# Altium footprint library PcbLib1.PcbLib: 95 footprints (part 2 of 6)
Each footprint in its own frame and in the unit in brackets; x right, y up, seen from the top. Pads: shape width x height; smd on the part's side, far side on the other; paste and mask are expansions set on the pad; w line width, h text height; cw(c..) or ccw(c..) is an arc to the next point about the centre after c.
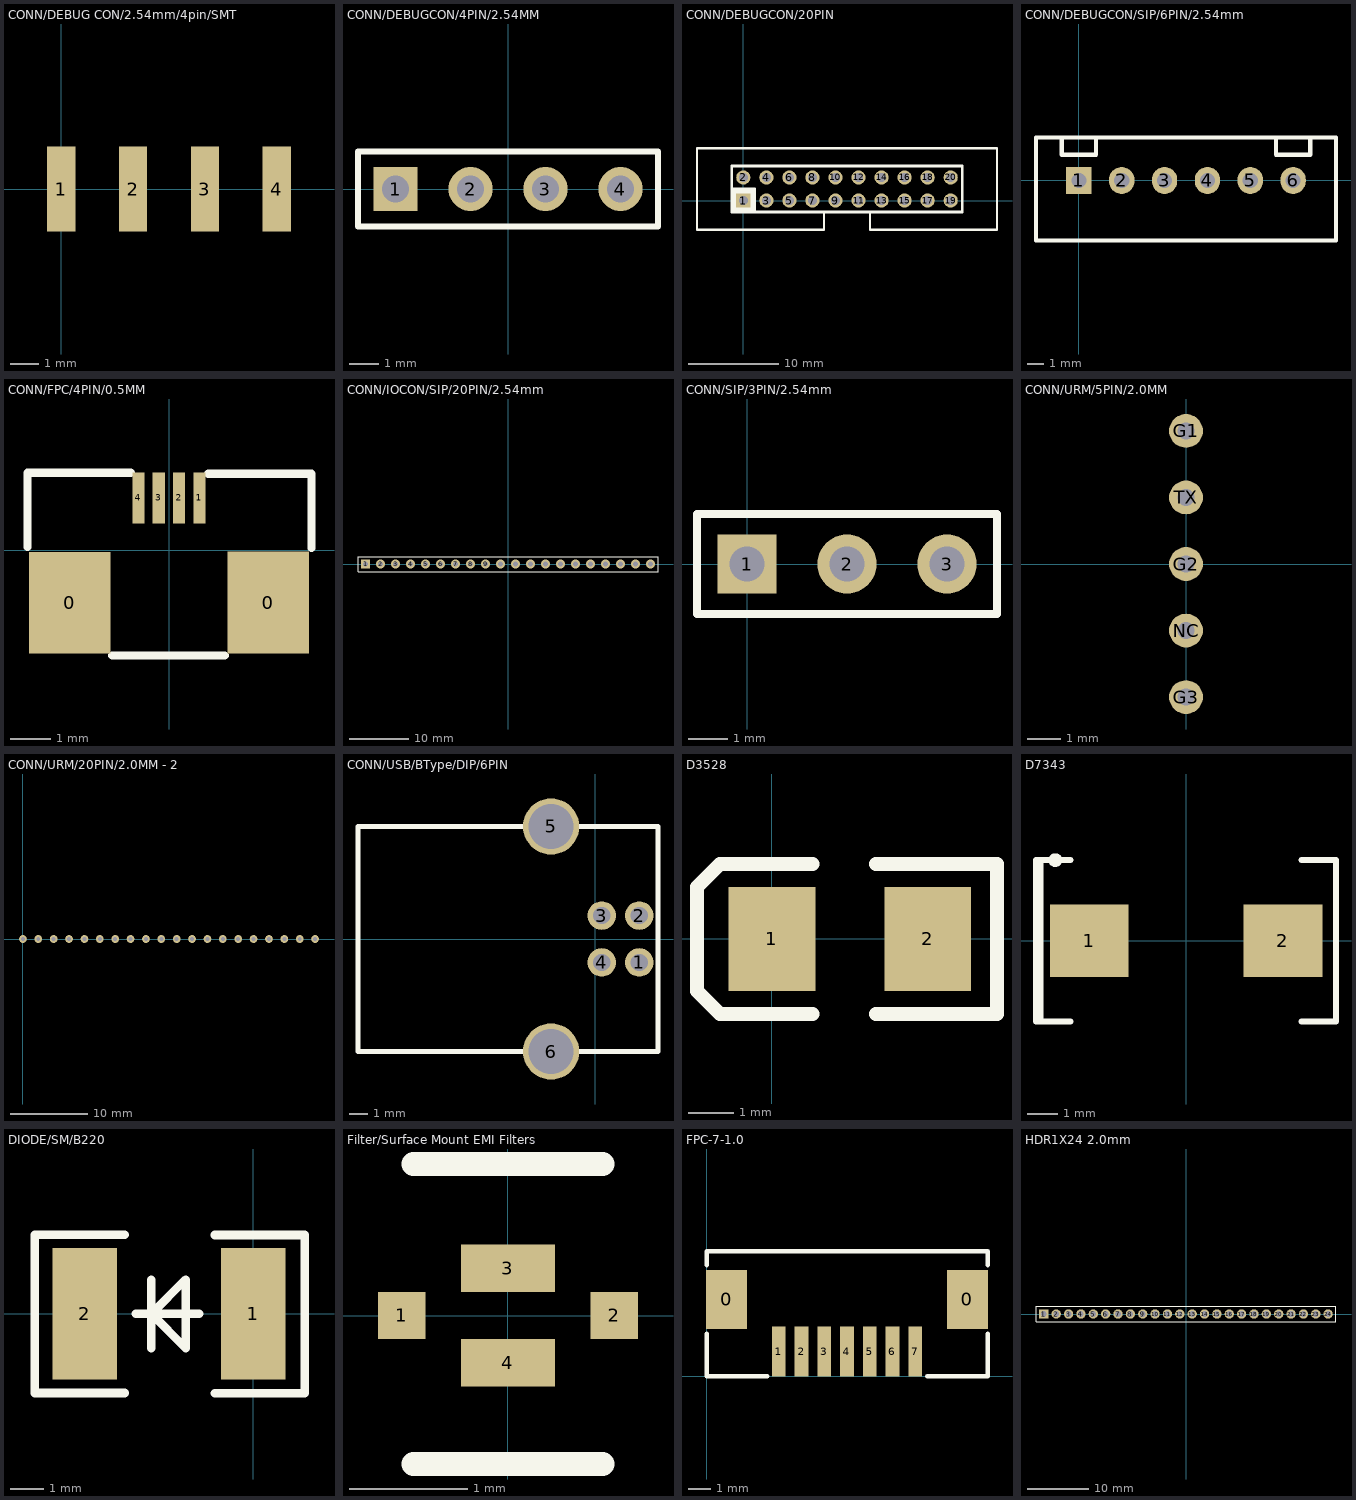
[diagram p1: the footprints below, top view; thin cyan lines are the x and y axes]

## CONN/DEBUG CON/2.54mm/4pin/SMT [mm]
pads (4):
  rect 1x3 smd paste+0 mask+0.1: 1(0,0) 2(2.54,0) 3(5.08,0) 4(7.62,0)

## CONN/DEBUGCON/4PIN/2.54MM [mm]
pads (4):
  rect 1.5x1.5 hole 0.9: 1(-3.81,0)
  round 1.5 hole 0.9: 2(-1.27,0) 3(1.27,0) 4(3.81,0)
Top Overlay:
  lines w0.2: -5.08,-1.27 5.08,-1.27 5.08,1.27 -5.08,1.27 -5.08,-1.27

## CONN/DEBUGCON/20PIN [mil]
pads (20):
  rect 62x62 hole 39.37: 1(0,0)
  round 62 hole 39.37: 2(0,100) 3(100,0) 4(100,100) 5(200,0) 6(200,100) 7(300,0) 8(300,100) 9(400,0) 10(400,100) 11(500,0) 12(500,100) 13(600,0) 14(600,100) 15(700,0) 16(700,100) 17(800,0) 18(800,100) 19(900,0) 20(900,100)
Top Overlay:
  rectangle: -50,-50 49,52
  lines w10: 350,-50 350,-127.17 -201.18,-127.17 -201.18,227.16 1101.18,227.16 1101.18,-127.17 550,-127.17 550,-50
  lines w12: -50,50 50,50 50,-50 ; -50,-50 950,-50 950,150 -50,150 -50,-50
3D body: height 352.36, standoff -114.17, extent -201,-123.27 1099,235

## CONN/DEBUGCON/SIP/6PIN/2.54mm [mm]
pads (6):
  rect 1.5x1.6 hole 0.9: 1(0,0)
  oval 1.5x1.6 hole 0.9: 2(2.54,0) 3(5.08,0) 4(7.62,0) 5(10.16,0) 6(12.7,0)
Top Overlay:
  lines w0.254: -1.016,2.54 -1.016,1.524 1.016,1.524 1.016,2.54 ; 11.684,2.54 11.684,1.524 13.716,1.524 13.716,2.54 ; -2.54,-3.556 -2.54,2.54 15.24,2.54 15.24,-3.556 -2.54,-3.556
3D body: height 7.51, standoff -2.49, extent -2.562,-3.562 12.518,2.438

## CONN/FPC/4PIN/0.5MM [mm]
pads (6):
  rect 2x2.5 smd paste+0 mask+0.1: 0(-2.439,-1.288) 0(2.439,-1.287)
  rect 0.3x1.25 smd paste+0 mask+0.04: 1(0.749,1.288) 2(0.249,1.288) 3(-0.251,1.288) 4(-0.751,1.288)
Top Overlay:
  lines w0.2: -3.48,0.076 -3.48,1.905 ; -3.454,1.905 -0.94,1.905 ; -1.397,-2.591 1.372,-2.591 ; 0.965,1.88 3.48,1.88 ; 3.505,0.051 3.505,1.88

## CONN/IOCON/SIP/20PIN/2.54mm [mm]
pads (20):
  rect 1.5x1.5 hole 0.9: 1(-24.13,0)
  round 1.5 hole 0.9: 2(-21.59,0) 3(-19.05,0) 4(-16.51,0) 5(-13.97,0) 6(-11.43,0) 7(-8.89,0) 8(-6.35,0) 9(-3.81,0) 10(-1.27,0) 11(1.27,0) 12(3.81,0) 13(6.35,0) 14(8.89,0) 15(11.43,0) 16(13.97,0) 17(16.51,0) 18(19.05,0) 19(21.59,0) 20(24.13,0)
Top Overlay:
  lines w0.2: -25.4,-1.27 -25.4,1.27 -23.495,1.27 25.4,1.27 25.4,-1.27 -25.4,-1.27
3D body: height 8.54, standoff -3, extent 12.7,-1.27 25.4,1.27
3D body: height 8.54, standoff -3, extent 0,-1.27 12.7,1.27
3D body: height 8.54, standoff -3, extent -12.7,-1.27 0,1.27
3D body: height 8.54, standoff -3, extent -25.4,-1.27 -12.7,1.27

## CONN/SIP/3PIN/2.54mm [mm]
pads (3):
  rect 1.5x1.5 hole 0.9: 1(0,0)
  round 1.5 hole 0.9: 2(2.54,0) 3(5.08,0)
Top Overlay:
  lines w0.2: -1.27,-1.27 -1.27,1.27 6.35,1.27 6.35,-1.27 -1.27,-1.27
3D body: height 8.54, standoff -3, extent -1.27,-1.27 6.35,1.27

## CONN/URM/5PIN/2.0MM [mil]
pads (5):
  round 40 hole 20 mask+2.5: G1(0,157.48) G2(0,0) G3(0,-157.48) NC(0,-78.74) TX(0,78.74)

## CONN/URM/20PIN/2.0MM - 2 [mil]
pads (20):
  round 40 hole 20 mask+2.5: 21(0,0) 22(78.74,0) 23(157.48,0) 24(236.22,0) 25(314.96,0) 26(393.7,0) 27(472.44,0) 28(551.18,0) 29(629.92,0) 30(708.66,0) 31(787.4,0) 32(866.14,0) 33(944.88,0) 34(1023.62,0) 35(1102.36,0) 36(1181.1,0) 37(1259.84,0) 38(1338.58,0) 39(1417.32,0) 40(1496.06,0)

## CONN/USB/BType/DIP/6PIN [mm]
pads (6):
  round 1.524 hole 0.92: 1(2.35,-1.25) 2(2.35,1.25) 3(0.35,1.25) 4(0.35,-1.25)
  round 3 hole 2.4: 5(-2.35,6) 6(-2.35,-6)
Top Overlay:
  lines w0.254: -12.65,-6 -12.65,6 3.35,6 3.35,-6 -12.65,-6
3D body: height 3.13, standoff -11.09, extent -13.036,-7.384 3.264,7.475

## D3528 [mil]
pads (2):
  rect 75x90 smd: 1(0,0) 2(135,0)
Top Overlay:
  lines w12: 35,-65 -45,-65 -65,-45 -65,45 -45,65 35,65 ; 90,-65 195,-65 195,65 90,65
3D body: height 74.8, standoff 0, extent 1,-55 138.8,55.24

## D7343 [mm]
pads (2):
  rect 2.6x2.4 smd: 1(-3.2,0) 2(3.2,0)
Top Overlay:
  circle w0.2: c-4.316,2.667 r0.125
  rectangle: -4.955,-2.666 -4.701,2.668
  lines w0.2: -3.81,-2.667 -4.953,-2.667 -4.953,2.667 -3.81,2.667 ; 3.81,-2.667 4.953,-2.667 4.953,2.667 3.81,2.667
3D body: height 2.9, standoff 0, extent -3.65,-2.15 3.65,2.15

## DIODE/SM/B220 [mm]
pads (2):
  rect 1.9x3.9 smd: 1(0,0) 2(-5,0)
Top Overlay:
  lines w0.254: -3.81,-2.349 -6.477,-2.349 -6.477,2.349 -3.81,2.349 ; -3.48,0 -1.6,0 ; -3.023,-1.016 -3.023,0 ; -3.023,1.016 -3.023,0 ; -1.143,-2.362 1.524,-2.362 1.524,2.337 -1.143,2.337 ; -3.023,0 -2.007,1.016 -2.007,-1.016 -3.023,0

## Filter/Surface Mount EMI Filters [mm]
pads (4):
  rect 0.4x0.4 smd paste+0 mask+0.1: 1(-0.9,0) 2(0.9,0)
  rect 0.8x0.4 smd paste+0 mask+0.065: 3(0,0.4) 4(0,-0.4)
Top Overlay:
  lines w0.2: -0.8,-1.257 0.8,-1.257 ; -0.8,1.283 0.8,1.283

## FPC-7-1.0 [mm]
pads (9):
  rect 1.8x2.6 smd: 0(0.875,3.392) 0(11.475,3.392)
  rect 0.6x2.2 smd: 1(3.175,1.092) 2(4.175,1.092) 3(5.175,1.092) 4(6.175,1.092) 5(7.175,1.092) 6(8.175,1.092) 7(9.175,1.092)
Top Overlay:
  lines w0.203: 0,1.88 0,0 2.667,0 ; 0,4.902 0,5.5 12.37,5.5 12.37,4.902 ; 9.703,0 12.37,0 12.37,1.88

## HDR1X24 2.0mm [mm]
pads (24):
  rect 1.5x1.5 hole 0.9: 1(-23,0)
  round 1.5 hole 0.9: 2(-21,0) 3(-19,0) 4(-17,0) 5(-15,0) 6(-13,0) 7(-11,0) 8(-9,0) 9(-7,0) 10(-5,0) 11(-3,0) 12(-1,0) 13(1,0) 14(3,0) 15(5,0) 16(7,0) 17(9,0) 18(11,0) 19(13,0) 20(15,0) 21(17,0) 22(19,0) 23(21,0) 24(23,0)
Top Overlay:
  lines w0.127: -24.27,-1.27 -24.27,1.27 24.27,1.27 24.27,-1.261 -24.261,-1.261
